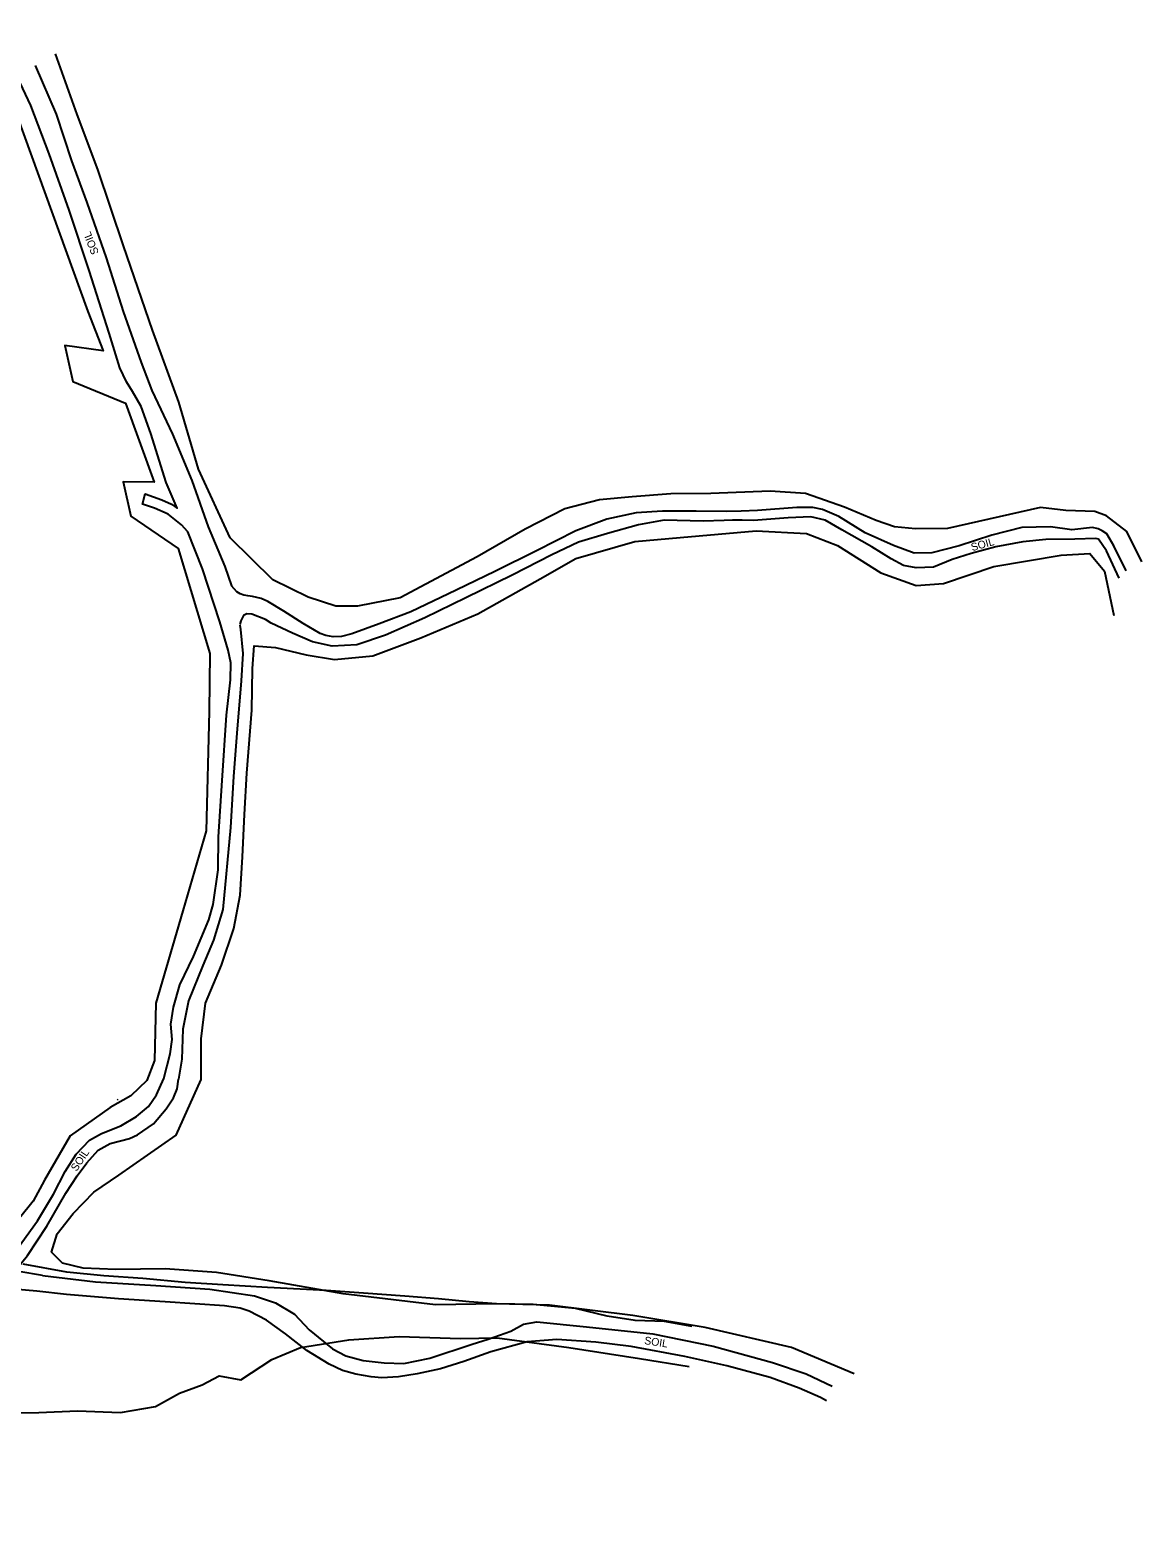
# Model space of a CAD drawing. Extents: x 2030130 to 2036320, y 723205 to 762423.
# Drawn here: x 2032106 to 2032679, y 757921 to 758699 of the extents above; entities that cross this region are included whole.
import ezdxf

# ---------------------------------------------------------------- set-up
doc = ezdxf.new("R2010")
doc.units = 0
for name, color, linetype in [('Draft_Station Labels Major', 7, 'Continuous'), ('Draft_Station Tics Major', 7, 'Continuous'), ('Old_Level_23', 7, 'Continuous')]:
    doc.layers.add(name, color=color, linetype=linetype)

msp = doc.modelspace()

# ---------------------------------------------------------------- linework, layer by layer
at = {"layer": 'Draft_Station Labels Major'}
for points in [[(2032108.61, 758681.23), (2032119.45, 758656.11), (2032127.36, 758632.02), (2032135.32, 758610.51), (2032145.31, 758582.01), (2032154.02, 758554.34), (2032163.34, 758527.9), (2032168.79, 758513.49), (2032179.49, 758490.99), (2032189.35, 758467.11), (2032197.87, 758443.07), (2032206.51, 758422.68), (2032209.96, 758412.64)], [(2032099.56, 758070.71), (2032109.8, 758084.98), (2032118.03, 758098.75), (2032124.03, 758110.39), (2032129.75, 758119.32), (2032136.64, 758126.56), (2032142.78, 758130), (2032152.72, 758133.89), (2032160.81, 758138.73), (2032167.09, 758143.93), (2032171.19, 758149.98), (2032174.89, 758158.41), (2032178.27, 758171.11), (2032179.24, 758178.54), (2032178.63, 758186.46), (2032180.04, 758195.27), (2032183.3, 758206.7), (2032190.24, 758221.3), (2032198.26, 758240.2), (2032200.37, 758248.24), (2032202.95, 758266.11), (2032203.24, 758283.17), (2032205.03, 758312.2), (2032207.31, 758345.99), (2032209.36, 758364.1), (2032209.48, 758372.93), (2032208.22, 758379.42), (2032203.84, 758394.16), (2032194.85, 758421.51), (2032187.38, 758440.61), (2032184.17, 758444.1), (2032177.22, 758449.73), (2032170.12, 758452.8), (2032163.93, 758454.75), (2032165.29, 758460.18), (2032173.96, 758457.02), (2032179, 758454.86), (2032181.86, 758452.75), (2032176.21, 758466.01), (2032168.33, 758491.39), (2032163.22, 758505.22), (2032158.8, 758513), (2032155.66, 758517.97), (2032152.31, 758525.28), (2032146.81, 758543.09), (2032136.39, 758575.47), (2032126.23, 758606.5), (2032115.89, 758635.58), (2032106.41, 758660.56), (2032099.41, 758675.16)], [(2032671.36, 758420.34), (2032665.06, 758433.28), (2032661.34, 758439.48), (2032659.01, 758441.08), (2032656.93, 758442.11), (2032653.97, 758442.85), (2032643.4, 758441.54), (2032632.26, 758443.21), (2032617.53, 758442.74), (2032602.14, 758438.79), (2032585.24, 758433.28), (2032571.04, 758429.63), (2032561.98, 758429.47), (2032551.41, 758433.43), (2032536.64, 758440.07), (2032523.14, 758448.52), (2032514.78, 758452.03), (2032509.68, 758453.11), (2032501.56, 758453.11), (2032481.11, 758451.64), (2032472.81, 758451.29), (2032465.13, 758450.98), (2032449.57, 758451.22), (2032432.22, 758451.2), (2032418.52, 758450.37), (2032403.39, 758447.06), (2032387.47, 758441), (2032367.26, 758430.75), (2032346.07, 758420.23), (2032325.76, 758410.41), (2032302.39, 758399.32), (2032286.11, 758393.05), (2032271.96, 758387.97), (2032266.62, 758386.47), (2032262.32, 758386.33), (2032258.55, 758387.07), (2032255.57, 758388.12), (2032246.81, 758393.25), (2032236.94, 758399.58), (2032228.66, 758404.59), (2032225.17, 758406.08), (2032222.98, 758406.63), (2032220.78, 758407.17), (2032218.33, 758407.49), (2032216.3, 758407.89), (2032214.41, 758408.47), (2032212.55, 758409.54), (2032209.92, 758412.75)], [(2032667.76, 758416.6), (2032661.18, 758430.82), (2032657.1, 758436.81), (2032655.67, 758437.17), (2032644.91, 758436.72), (2032629.97, 758436.61), (2032617.99, 758435.35), (2032604.06, 758432.75), (2032591.46, 758429.42), (2032581.53, 758426.22), (2032571.93, 758422.33), (2032563.03, 758422.03), (2032556.54, 758423.25), (2032550.08, 758426.59), (2032540.18, 758432.82), (2032524.74, 758441.65), (2032516.15, 758446.65), (2032508.76, 758448.29), (2032496.94, 758447.7), (2032479.17, 758446.37), (2032473.22, 758446.54), (2032468.38, 758446.64), (2032463.94, 758446.33), (2032453.13, 758446.09), (2032433.09, 758446.65), (2032419.79, 758444.2), (2032403.85, 758439.67), (2032388.87, 758435.3), (2032375.14, 758428.7), (2032354.64, 758418.11), (2032330.75, 758406.55), (2032309.68, 758396.1), (2032289.32, 758387.3), (2032274.48, 758382.3), (2032261.83, 758381.61), (2032251.64, 758383.85), (2032241.26, 758388.18), (2032230.31, 758393.45), (2032227.37, 758395.28)], [(2032214.21, 758392.37), (2032214.58, 758390.09), (2032215.8, 758377.83), (2032214.92, 758363.61), (2032212.57, 758336.71), (2032210.95, 758314.31), (2032209.32, 758287.93), (2032205.42, 758245.69), (2032200.66, 758229.85), (2032195.08, 758216.71), (2032187.71, 758198.43), (2032184.76, 758183.84), (2032184.28, 758168.42), (2032182.53, 758158.01)], [(2032227.37, 758395.28), (2032220.45, 758398.03), (2032217.85, 758398.17), (2032216.13, 758397.38), (2032214.62, 758394.62), (2032214.15, 758392.75)], [(2032112.32, 758056.69), (2032100.2, 758058.83), (2032099.24, 758059.76), (2032099.57, 758060.68), (2032104.66, 758067.07), (2032114.69, 758082.09), (2032124.37, 758099.28), (2032130.28, 758108.16), (2032135.23, 758114.79), (2032141.18, 758121.47), (2032147.3, 758124.82), (2032157.21, 758127.41), (2032161.47, 758129.33), (2032169.56, 758134.98), (2032176.26, 758142.66), (2032180.01, 758148.49), (2032181.84, 758153.02), (2032182.53, 758158.01)], [(2032516.79, 757992.06), (2032513.66, 757993.71), (2032502.74, 757998.63), (2032487.75, 758003.98), (2032465.38, 758010.08), (2032443.77, 758014.89), (2032415.99, 758020.06), (2032397.74, 758022.33), (2032377.77, 758023.75), (2032362.42, 758022.51), (2032343.68, 758017.24), (2032329.71, 758012.38), (2032317.71, 758008.61), (2032305.69, 758005.94), (2032296.04, 758004.37), (2032287.37, 758003.95), (2032281.91, 758004.42), (2032273.99, 758005.81), (2032267.08, 758007.64), (2032260.24, 758010.95), (2032248.67, 758018.03), (2032237.68, 758026.65), (2032227.98, 758033.66), (2032218.99, 758038.3), (2032214.37, 758039.76), (2032206.24, 758041.1), (2032175.69, 758043.17), (2032151.55, 758044.63), (2032124.81, 758046.82), (2032109.44, 758048.68), (2032092.01, 758050.25)], [(2032112.32, 758056.69), (2032139.81, 758053.49), (2032170.79, 758051.51), (2032198.69, 758049.6), (2032221.75, 758046.22), (2032232.59, 758042.61), (2032242.39, 758036.77), (2032250, 758028.59), (2032261.92, 758018.94), (2032268.79, 758015.32), (2032277.71, 758012.79), (2032288.56, 758011.57), (2032298.85, 758011.28), (2032312.18, 758014.02), (2032334.09, 758021.18), (2032342.34, 758023.9), (2032353.91, 758027.97), (2032360.41, 758031.63), (2032367.37, 758032.77), (2032393.02, 758030.23), (2032427.28, 758026.64), (2032458.34, 758020.25), (2032488.9, 758011.81), (2032506.23, 758005.87), (2032519.71, 757999.52)]]:
    msp.add_lwpolyline(points, dxfattribs=at)
at = {"layer": 'Draft_Station Tics Major'}
msp.add_line((2032151.27, 758147.49), (2032150.86, 758147.21), dxfattribs=at)
for points in [[(2032080.81, 758699.49), (2032098.94, 758655.9), (2032135.8, 758554.33), (2032143.71, 758533.92), (2032123.97, 758536.66), (2032127.97, 758518.23), (2032155.2, 758507.01), (2032170.03, 758466.24), (2032154.06, 758466.44), (2032158.01, 758448.62), (2032182.38, 758431.92), (2032198.67, 758377.77), (2032198.38, 758347.8), (2032196.8, 758286.3), (2032184.82, 758244.89), (2032170.78, 758197.22)], [(2032679.43, 758425.05), (2032671.74, 758440.65), (2032661.19, 758448.77), (2032655.17, 758451.13), (2032640.28, 758451.61), (2032627.24, 758453.07), (2032579.24, 758442.22), (2032562.77, 758442.09), (2032551.89, 758443.19), (2032542.34, 758446.39), (2032526.02, 758453.32), (2032505.88, 758460.39), (2032487.69, 758461.49), (2032457.19, 758460.4), (2032436.43, 758460.12), (2032416.57, 758458.6), (2032399.77, 758457.13), (2032381.77, 758452.5), (2032361.29, 758442.01), (2032336.61, 758427.7), (2032296.79, 758406.42), (2032274.83, 758402.18), (2032263.66, 758402.14), (2032249.44, 758406.91), (2032231.16, 758415.75), (2032209.21, 758437.48), (2032192.89, 758472.81), (2032182.69, 758507.42), (2032169.1, 758544.7), (2032154.22, 758588.19), (2032140.96, 758627.62), (2032130.19, 758655.88), (2032119.17, 758687.25)], [(2032531.05, 758005.95), (2032498.72, 758019.61), (2032454.24, 758029.95), (2032416.86, 758036.13), (2032373.87, 758041.33), (2032346.44, 758042.04), (2032315.13, 758041.54), (2032267.51, 758047.3), (2032229.24, 758053.9), (2032202.14, 758058.31), (2032175.6, 758060.18), (2032150.27, 758059.77), (2032133.35, 758060.43), (2032122.7, 758063.1), (2032116.96, 758068.71), (2032119.95, 758078.29), (2032128.13, 758088.75), (2032138.83, 758099.78), (2032151.74, 758108.46), (2032181.32, 758129.06), (2032194.28, 758157.8), (2032194.19, 758178.87), (2032196.39, 758197.19), (2032204.72, 758216.95), (2032211.03, 758235.83), (2032214.35, 758253.07), (2032215.53, 758272.84), (2032216.61, 758294.61), (2032217.79, 758315.97), (2032220.37, 758348.49), (2032220.79, 758370.03), (2032221.55, 758381.76), (2032232.62, 758380.78), (2032248.37, 758377.03), (2032263.09, 758374.74), (2032282.81, 758376.56), (2032307.58, 758385.85), (2032336.88, 758398.17), (2032369.04, 758416.34), (2032387.55, 758426.8), (2032417.92, 758435.48), (2032441.29, 758437.58), (2032480.5, 758441.07), (2032506.38, 758439.75), (2032522.5, 758433.53), (2032544.79, 758419.41), (2032563.01, 758412.87), (2032577.17, 758413.89), (2032603.02, 758422.71), (2032637.83, 758428.5), (2032652.55, 758429.38), (2032660.21, 758420.31), (2032664.94, 758397.4)], [(2032170.78, 758197.22), (2032170.24, 758167.7), (2032166.26, 758157.37), (2032157.94, 758149.51), (2032147.27, 758143.44), (2032126.69, 758128.71), (2032113.45, 758105.99), (2032107.55, 758095.14), (2032093.42, 758077.6), (2032083.27, 758071.99), (2032065.17, 758071.95), (2032043.86, 758080.09), (2032038.57, 758077.33)], [(2032447.48, 758030.39), (2032433.17, 758033.02), (2032418.11, 758033.45), (2032403.57, 758035.77), (2032387.3, 758039.64), (2032365.49, 758041.72), (2032346.62, 758042.16), (2032332.4, 758043.1), (2032316.6, 758044.69), (2032299.27, 758046.1), (2032278, 758047.66), (2032258.75, 758048.96), (2032228.44, 758050.53), (2032205.42, 758051.92), (2032185.93, 758053.15), (2032164.12, 758055.09), (2032144.1, 758056.61), (2032125, 758058.45), (2032102.39, 758062.48)], [(2032053.23, 757921.3), (2032059.03, 757933.45), (2032063.79, 757952.49), (2032068.31, 757971.71), (2032076.61, 757981.23), (2032091.31, 757985.86), (2032110.53, 757985.95), (2032130.39, 757986.8), (2032152.69, 757986.04), (2032170.62, 757989.17), (2032183.08, 757996.01), (2032194.81, 758000.33), (2032203.59, 758004.86), (2032214.67, 758002.86), (2032230.73, 758013.34), (2032245.39, 758019.51), (2032270.43, 758023.47), (2032296.34, 758025.25), (2032327.98, 758024.22), (2032346.89, 758024.56), (2032383.95, 758019.53), (2032420.34, 758013.85), (2032445.92, 758009.73)]]:
    msp.add_lwpolyline(points, dxfattribs=at)

# ---------------------------------------------------------------- texts
at = {"layer": 'Old_Level_23'}
for rotation, p in [(111.81254, (2032141.55, 758584.61)), (15.58591, (2032591.93, 758430.55)), (56.46073, (2032129.99, 758110.14)), (351.32599, (2032422.61, 758021.32))]:
    msp.add_text('SOIL', height=4, rotation=rotation, dxfattribs=at).set_placement(p)

doc.saveas('drawing.dxf')
